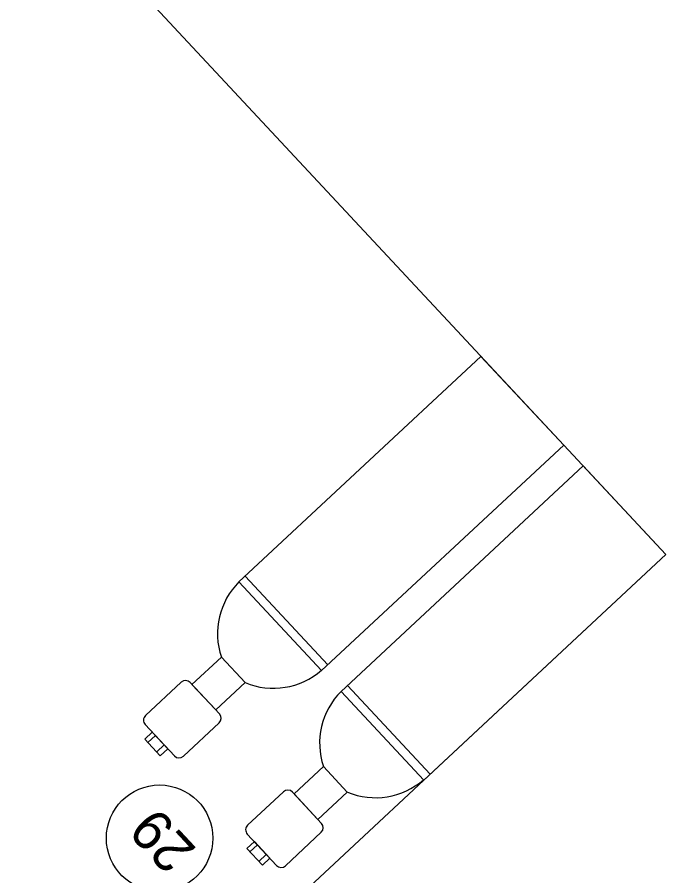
# Model space of a CAD drawing. Extents: x 1121979 to 1130574, y 1838676 to 1848573.
# Drawn here: x 1129664.18 to 1129668.04, y 1839356.88 to 1839361.99 of the extents above; entities that cross this region are included whole.
import ezdxf

# ---------------------------------------------------------------- set-up
doc = ezdxf.new("R2010")
doc.units = 0
for name, color, linetype in [('IPDC BUILDING RELATED', 7, 'Continuous'), ('IPDC-EXIST ELECT EQUIP', 7, 'Continuous'), ('Level 4', 7, 'Continuous')]:
    doc.layers.add(name, color=color, linetype=linetype)

msp = doc.modelspace()

# ---------------------------------------------------------------- linework, layer by layer
at = {"layer": 'IPDC BUILDING RELATED'}
for q in [(1129648.6826, 1839379.5567), (1129661.457, 1839352.6561)]:
    msp.add_line((1129668.0394, 1839358.7937), q, dxfattribs=at)
at = {"layer": 'IPDC-EXIST ELECT EQUIP'}
for p, q in [((1129666.941, 1839359.9719), (1129665.5025, 1839358.6306)), ((1129666.941, 1839359.9719), (1129667.4325, 1839359.4447)), ((1129667.4325, 1839359.4447), (1129665.994, 1839358.1034)), ((1129667.5479, 1839359.3208), (1129666.1094, 1839357.9796)), ((1129667.5479, 1839359.3208), (1129668.0394, 1839358.7937)), ((1129668.0394, 1839358.7937), (1129666.6009, 1839357.4524)), ((1129665.5025, 1839358.6306), (1129665.994, 1839358.1034)), ((1129665.5401, 1839358.6656), (1129666.0316, 1839358.1385)), ((1129664.947, 1839357.8356), (1129665.16, 1839358.0341)), ((1129665.2131, 1839358.0323), (1129665.3869, 1839357.8459)), ((1129666.147, 1839358.0146), (1129666.6385, 1839357.4874)), ((1129666.1094, 1839357.9796), (1129666.6009, 1839357.4524)), ((1129664.9452, 1839357.7825), (1129665.119, 1839357.5961)), ((1129665.1721, 1839357.5942), (1129665.385, 1839357.7927)), ((1129664.9612, 1839357.6758), (1129665.0059, 1839357.7174)), ((1129665.0135, 1839357.6196), (1129665.0582, 1839357.6613)), ((1129665.554, 1839357.1846), (1129665.7669, 1839357.3831)), ((1129665.82, 1839357.3812), (1129665.9938, 1839357.1949)), ((1129665.5521, 1839357.1314), (1129665.7259, 1839356.9451)), ((1129665.779, 1839356.9432), (1129665.992, 1839357.1417)), ((1129665.5681, 1839357.0247), (1129665.6128, 1839357.0664)), ((1129665.6204, 1839356.9686), (1129665.6651, 1839357.0103))]:
    msp.add_line(p, q, dxfattribs=at)
for points in [[(1129665.2233, 1839358.0213), (1129665.3651, 1839357.8692), (1129665.5397, 1839358.032), (1129665.3978, 1839358.1841)], [(1129664.9424, 1839357.696), (1129665.035, 1839357.5966), (1129665.0797, 1839357.6382), (1129664.987, 1839357.7376)], [(1129665.8302, 1839357.3703), (1129665.972, 1839357.2182), (1129666.1466, 1839357.381), (1129666.0047, 1839357.5331)], [(1129665.5493, 1839357.0449), (1129665.642, 1839356.9455), (1129665.6866, 1839356.9872), (1129665.5939, 1839357.0866)]]:
    msp.add_lwpolyline(points, close=True, dxfattribs=at)
for centre, radius, start, end in [((1129665.809, 1839358.3232), 0.4341, 134.9201, 198.6864), ((1129665.7071, 1839358.4325), 0.4341, 247.3079, 311.0742), ((1129665.1856, 1839358.0066), 0.0376, 42.9971, 132.9971), ((1129666.416, 1839357.6722), 0.4341, 134.9201, 198.6864), ((1129664.9727, 1839357.8081), 0.0376, 132.9971, 222.9971), ((1129665.3594, 1839357.8202), 0.0376, 312.9971, 42.9971), ((1129665.1465, 1839357.6217), 0.0376, 222.9971, 312.9971), ((1129666.3141, 1839357.7815), 0.4341, 247.3079, 311.0742), ((1129665.7925, 1839357.3556), 0.0376, 42.9971, 132.9971), ((1129665.5796, 1839357.1571), 0.0376, 132.9971, 222.9971), ((1129665.9663, 1839357.1692), 0.0376, 312.9971, 42.9971), ((1129665.7534, 1839356.9707), 0.0376, 222.9971, 312.9971)]:
    msp.add_arc(centre, radius, start, end, dxfattribs=at)
at = {"layer": 'Level 4'}
msp.add_circle((1129665.0309, 1839357.1069), 0.3163, dxfattribs=at)

# ---------------------------------------------------------------- texts
msp.add_text('29', height=0.24, rotation=132.9971, dxfattribs=at).set_placement((1129665.2561, 1839357.0413))

doc.saveas('drawing.dxf')
